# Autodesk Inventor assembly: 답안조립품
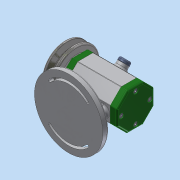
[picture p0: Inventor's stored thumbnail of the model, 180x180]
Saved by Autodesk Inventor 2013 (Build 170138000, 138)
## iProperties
Created: 2017-06
Part Number: 답안조립품
Document SubType Name: Assembly
Designer: dgall
Author: dgall
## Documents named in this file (14)
- C:\Users\dgall\Desktop\470607V1021\답안조립품.iam
- C:\Users\dgall\Desktop\470607V1021\V벨트풀리.ipt
- C:\Users\dgall\Desktop\470607V1021\고무캡.ipt
- C:\Users\dgall\Desktop\470607V1021\너트 M 8.ipt
- C:\Users\dgall\Desktop\470607V1021\뒤커버.ipt
- C:\Users\dgall\Desktop\470607V1021\베어링 15 x 32 x 9.ipt
- C:\Users\dgall\Desktop\470607V1021\본체.ipt
- C:\Users\dgall\Desktop\470607V1021\볼트 M4 x 12.ipt
- C:\Users\dgall\Desktop\470607V1021\스프링와셔 8.ipt
- C:\Users\dgall\Desktop\470607V1021\앞커버.ipt
- C:\Users\dgall\Desktop\470607V1021\오일 실 15 25 7.ipt
- C:\Users\dgall\Desktop\470607V1021\와셔 8x17.ipt
- C:\Users\dgall\Desktop\470607V1021\축.ipt
- C:\Users\dgall\Desktop\470607V1021\키 3 x 3 x 12.ipt
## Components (2 placed, 2 different names)
1. V벨트풀리:1 — 각도:2
2. 고무캡:1
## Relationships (1: Angle 1)
- 각도:2 [Angle]: V벨트풀리:1
